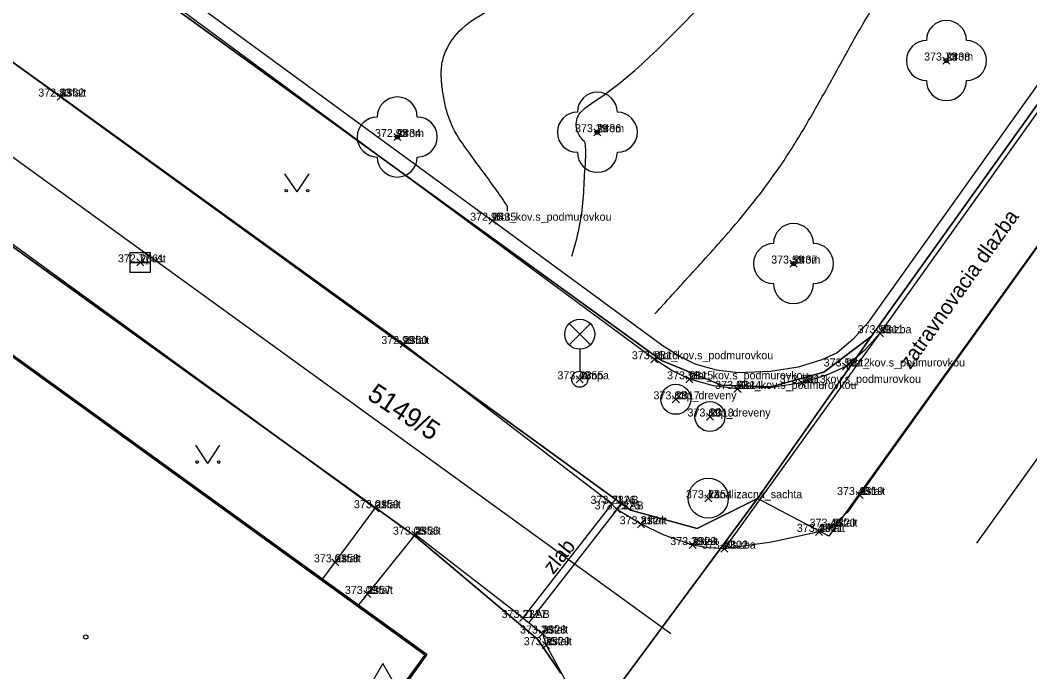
# Model space of a CAD drawing. Extents: x -400488 to -400124, y -1251493 to -1251223.
# Drawn here: x -400314.45 to -400289.23, y -1251399.85 to -1251383.58 of the extents above; entities that cross this region are included whole.
import ezdxf

# ---------------------------------------------------------------- set-up
doc = ezdxf.new("R2010")
doc.units = 0
for name, color, linetype in [('Level 20', 7, 'Continuous'), ('Level 21', 7, 'Continuous'), ('Level 22', 7, 'Continuous'), ('Level 23', 7, 'Continuous'), ('Level 31', 7, 'Continuous'), ('Level 32', 7, 'Continuous'), ('Level 34', 7, 'Continuous'), ('Level 35', 7, 'Continuous'), ('Level 36', 7, 'Continuous'), ('Level 49', 7, 'Continuous'), ('Level 50', 7, 'Continuous'), ('Level 52', 7, 'Continuous'), ('Level 53', 7, 'Continuous'), ('Level 54', 7, 'Continuous'), ('Level 63', 7, 'Continuous')]:
    doc.layers.add(name, color=color, linetype=linetype)

msp = doc.modelspace()

# ---------------------------------------------------------------- linework, layer by layer
at = {"layer": 'Level 20'}
for p, q in [((-400291.398, -1251384.678), (-400291.222, -1251384.502)), ((-400291.222, -1251384.678), (-400291.398, -1251384.502)), ((-400313.528, -1251385.578), (-400313.352, -1251385.402)), ((-400313.352, -1251385.578), (-400313.528, -1251385.402)), ((-400300.118, -1251386.468), (-400299.942, -1251386.292)), ((-400299.942, -1251386.468), (-400300.118, -1251386.292)), ((-400305.118, -1251386.588), (-400304.942, -1251386.412)), ((-400304.942, -1251386.588), (-400305.118, -1251386.412)), ((-400302.738, -1251388.678), (-400302.562, -1251388.502)), ((-400302.562, -1251388.678), (-400302.738, -1251388.502)), ((-400311.538, -1251389.718), (-400311.362, -1251389.542)), ((-400311.362, -1251389.718), (-400311.538, -1251389.542)), ((-400295.218, -1251389.748), (-400295.042, -1251389.572)), ((-400295.042, -1251389.748), (-400295.218, -1251389.572)), ((-400293.058, -1251391.488), (-400292.882, -1251391.312)), ((-400292.882, -1251391.488), (-400293.058, -1251391.312)), ((-400304.958, -1251391.758), (-400304.782, -1251391.582)), ((-400304.782, -1251391.758), (-400304.958, -1251391.582)), ((-400298.698, -1251392.138), (-400298.522, -1251391.962)), ((-400298.522, -1251392.138), (-400298.698, -1251391.962)), ((-400293.908, -1251392.318), (-400293.732, -1251392.142)), ((-400293.732, -1251392.318), (-400293.908, -1251392.142)), ((-400300.558, -1251392.638), (-400300.382, -1251392.462)), ((-400300.382, -1251392.638), (-400300.558, -1251392.462)), ((-400297.818, -1251392.638), (-400297.642, -1251392.462)), ((-400297.642, -1251392.638), (-400297.818, -1251392.462)), ((-400295.008, -1251392.728), (-400294.832, -1251392.552)), ((-400294.832, -1251392.728), (-400295.008, -1251392.552)), ((-400296.618, -1251392.878), (-400296.442, -1251392.702)), ((-400296.442, -1251392.878), (-400296.618, -1251392.702)), ((-400298.158, -1251393.138), (-400297.982, -1251392.962)), ((-400297.982, -1251393.138), (-400298.158, -1251392.962)), ((-400297.308, -1251393.568), (-400297.132, -1251393.392)), ((-400297.132, -1251393.568), (-400297.308, -1251393.392)), ((-400293.568, -1251395.528), (-400293.392, -1251395.352)), ((-400293.392, -1251395.528), (-400293.568, -1251395.352)), ((-400299.758, -1251395.748), (-400299.582, -1251395.572)), ((-400299.582, -1251395.748), (-400299.758, -1251395.572)), ((-400297.348, -1251395.608), (-400297.172, -1251395.432)), ((-400297.172, -1251395.608), (-400297.348, -1251395.432)), ((-400305.668, -1251395.858), (-400305.492, -1251395.682)), ((-400305.492, -1251395.858), (-400305.668, -1251395.682)), ((-400299.628, -1251395.888), (-400299.452, -1251395.712)), ((-400299.452, -1251395.888), (-400299.628, -1251395.712)), ((-400299.028, -1251396.258), (-400298.852, -1251396.082)), ((-400298.852, -1251396.258), (-400299.028, -1251396.082)), ((-400304.668, -1251396.518), (-400304.492, -1251396.342)), ((-400304.492, -1251396.518), (-400304.668, -1251396.342)), ((-400294.578, -1251396.448), (-400294.402, -1251396.272)), ((-400294.402, -1251396.448), (-400294.578, -1251396.272)), ((-400294.258, -1251396.318), (-400294.082, -1251396.142)), ((-400294.082, -1251396.318), (-400294.258, -1251396.142)), ((-400297.738, -1251396.778), (-400297.562, -1251396.602)), ((-400297.562, -1251396.778), (-400297.738, -1251396.602)), ((-400296.948, -1251396.868), (-400296.772, -1251396.692)), ((-400296.772, -1251396.868), (-400296.948, -1251396.692)), ((-400306.668, -1251397.208), (-400306.492, -1251397.032)), ((-400306.492, -1251397.208), (-400306.668, -1251397.032)), ((-400305.868, -1251397.998), (-400305.692, -1251397.822)), ((-400305.692, -1251397.998), (-400305.868, -1251397.822)), ((-400301.978, -1251398.598), (-400301.802, -1251398.422)), ((-400301.802, -1251398.598), (-400301.978, -1251398.422)), ((-400301.488, -1251398.988), (-400301.312, -1251398.812)), ((-400301.312, -1251398.988), (-400301.488, -1251398.812)), ((-400301.398, -1251399.278), (-400301.222, -1251399.102)), ((-400301.222, -1251399.278), (-400301.398, -1251399.102))]:
    msp.add_line(p, q, dxfattribs=at)
at = {"layer": 'Level 31'}
for points in [[(-400292.97, -1251391.4), (-400296.86, -1251396.78)], [(-400299.67, -1251395.66), (-400301.89, -1251398.51)], [(-400299.54, -1251395.8), (-400301.742, -1251398.627)]]:
    msp.add_lwpolyline(points, dxfattribs=at)
at = {"layer": 'Level 32'}
msp.add_line((-400290.55, -1251396.645), (-400264.548, -1251360.319), dxfattribs=at)
for points in [[(-400270.68, -1251354.37), (-400269.393, -1251355.452), (-400268.89, -1251355.918), (-400268.52, -1251356.37), (-400268.265, -1251356.83), (-400268.08, -1251357.34), (-400267.96, -1251358.23), (-400267.913, -1251358.721), (-400267.9, -1251359.2), (-400268.092, -1251359.586), (-400270.52, -1251363.46), (-400278.03, -1251373.86), (-400293.48, -1251395.44), (-400293.769, -1251395.863), (-400294.17, -1251396.23), (-400294.49, -1251396.36), (-400295.676, -1251396.619), (-400296.86, -1251396.78), (-400297.255, -1251396.759), (-400297.65, -1251396.69), (-400298.36, -1251396.445), (-400298.94, -1251396.17), (-400299.54, -1251395.8), (-400299.67, -1251395.66)], [(-400313.44, -1251385.49), (-400321.58, -1251379.65), (-400332, -1251372.55)], [(-400298.195, -1251398.906), (-400330.918, -1251375.214)], [(-400331.04, -1251377.23), (-400305.58, -1251395.77), (-400331.355, -1251377.021), (-400331.659, -1251376.849), (-400331.92, -1251376.772), (-400332.18, -1251376.74), (-400332.684, -1251376.866), (-400333.069, -1251377.004), (-400333.432, -1251377.178), (-400333.85, -1251377.49), (-400335, -1251379.01), (-400336.633, -1251381.335)], [(-400299.67, -1251395.66), (-400304.87, -1251391.67), (-400313.44, -1251385.49)], [(-400306.913, -1251397.57), (-400305.58, -1251395.77)], [(-400301.89, -1251398.51), (-400304.58, -1251396.43), (-400306.025, -1251398.213)], [(-400301.89, -1251398.51), (-400301.4, -1251398.9), (-400301.31, -1251399.19), (-400300.26, -1251401.11), (-400300.19, -1251401.36), (-400300.045, -1251402.48), (-400299.98, -1251403.97), (-400300.164, -1251404.567), (-400300.47, -1251405.17), (-400303.28, -1251409.37)]]:
    msp.add_lwpolyline(points, dxfattribs=at)
at = {"layer": 'Level 34'}
msp.add_lwpolyline([(-400333.76, -1251378.15), (-400304.338, -1251399.434), (-400304.338, -1251399.434), (-400309.014, -1251405.829)], dxfattribs=at)
at = {"layer": 'Level 35'}
for points in [[(-400330.938, -1251368.394), (-400330.78, -1251368.19), (-400329.16, -1251369.12), (-400314.31, -1251380.06), (-400302.65, -1251388.59)], [(-400279.695, -1251372.087), (-400293.283, -1251391.15), (-400293.637, -1251391.547), (-400294.036, -1251391.888), (-400294.424, -1251392.061), (-400295.012, -1251392.25), (-400295.704, -1251392.357), (-400296.513, -1251392.389), (-400297.052, -1251392.322), (-400297.586, -1251392.175), (-400297.973, -1251391.981), (-400298.384, -1251391.72), (-400302.65, -1251388.59)], [(-400279.37, -1251372.32), (-400292.97, -1251391.4), (-400293.356, -1251391.833), (-400293.82, -1251392.23), (-400294.281, -1251392.435), (-400294.92, -1251392.64), (-400295.666, -1251392.756), (-400296.53, -1251392.79), (-400297.13, -1251392.716), (-400297.73, -1251392.55), (-400298.17, -1251392.329), (-400298.61, -1251392.05), (-400311.61, -1251382.45), (-400320.06, -1251376.29)]]:
    msp.add_lwpolyline(points, dxfattribs=at)
at = {"layer": 'Level 36'}
for p, q in [((-400307.534, -1251387.87), (-400307.834, -1251387.42)), ((-400307.534, -1251387.87), (-400307.234, -1251387.42)), ((-400309.758, -1251394.649), (-400310.058, -1251394.199)), ((-400309.758, -1251394.649), (-400309.458, -1251394.199))]:
    msp.add_line(p, q, dxfattribs=at)
for centre, radius in [((-400291.31, -1251384.59), 0.05), ((-400305.03, -1251386.5), 0.05), ((-400300.03, -1251386.38), 0.05), ((-400307.804, -1251387.84), 0.03), ((-400307.264, -1251387.84), 0.03), ((-400295.13, -1251389.66), 0.05), ((-400310.028, -1251394.619), 0.03), ((-400309.488, -1251394.619), 0.03)]:
    msp.add_circle(centre, radius, dxfattribs=at)
for centre, start, end in [((-400291.31, -1251384.09), 0, 180), ((-400291.81, -1251384.59), 90, 270), ((-400290.81, -1251384.59), 270, 90), ((-400291.31, -1251385.09), 180, 0), ((-400305.03, -1251386), 0, 180), ((-400300.03, -1251385.88), 0, 180), ((-400305.53, -1251386.5), 90, 270), ((-400304.53, -1251386.5), 270, 90), ((-400300.53, -1251386.38), 90, 270), ((-400299.53, -1251386.38), 270, 90), ((-400305.03, -1251387), 180, 0), ((-400300.03, -1251386.88), 180, 0), ((-400295.13, -1251389.16), 0, 180), ((-400295.63, -1251389.66), 90, 270), ((-400294.63, -1251389.66), 270, 90), ((-400295.13, -1251390.16), 180, 0)]:
    msp.add_arc(centre, 0.5, start, end, dxfattribs=at)
at = {"layer": 'Level 49'}
for points in [[(-400298.594, -1251390.918), (-400297.579, -1251389.803), (-400296.576, -1251388.675), (-400295.294, -1251386.973), (-400294.717, -1251386.031), (-400294.176, -1251385.068), (-400293.64, -1251384.103), (-400293.079, -1251383.154), (-400292.558, -1251382.354), (-400292.017, -1251381.567), (-400291.474, -1251380.779), (-400290.946, -1251379.978), (-400290.936, -1251379.958), (-400290.353, -1251377.108), (-400290.345, -1251377.073), (-400289.148, -1251371.673), (-400289.131, -1251371.633), (-400288.68, -1251369.757), (-400288.682, -1251369.751), (-400289.179, -1251365.184), (-400289.187, -1251365.045), (-400289.199, -1251364.086), (-400289.178, -1251363.127), (-400289.151, -1251362.167), (-400289.146, -1251361.208), (-400289.326, -1251359.947), (-400289.998, -1251358.61), (-400290.194, -1251358.383), (-400290.2, -1251358.378), (-400291.608, -1251356.855), (-400292.307, -1251356.088), (-400293.021, -1251355.336), (-400293.116, -1251355.24), (-400296.365, -1251351.788), (-400297.616, -1251350.178), (-400299.549, -1251347.891), (-400299.559, -1251347.877), (-400299.595, -1251347.847), (-400301.142, -1251346.859), (-400302.556, -1251345.879), (-400307.962, -1251342.189), (-400307.971, -1251342.179), (-400307.982, -1251342.152), (-400308.883, -1251340.471), (-400309.528, -1251339.56), (-400310.26, -1251338.706), (-400310.968, -1251337.837), (-400311.406, -1251337.164)], [(-400300.667, -1251389.478), (-400300.483, -1251388.773), (-400300.384, -1251388.062), (-400300.344, -1251387.35), (-400300.339, -1251386.641), (-400300.34, -1251386.636), (-400300.362, -1251386.605), (-400300.534, -1251386.354), (-400300.515, -1251385.99), (-400300.109, -1251385.615), (-400297.14, -1251382.932), (-400297.057, -1251382.855), (-400295.589, -1251381.52), (-400295.422, -1251381.289), (-400295.284, -1251381.059), (-400295.265, -1251381.015), (-400294.968, -1251379.948), (-400294.642, -1251379.013), (-400294.274, -1251378.09), (-400293.924, -1251377.161), (-400293.647, -1251376.207), (-400293.646, -1251376.19), (-400293.641, -1251376.158), (-400292.799, -1251374.602), (-400292.78, -1251374.568), (-400292.201, -1251371.517), (-400292.573, -1251371.086), (-400292.863, -1251370.616), (-400292.873, -1251370.59), (-400293.119, -1251369.55), (-400293.291, -1251368.49), (-400293.49, -1251367.439), (-400293.821, -1251366.425), (-400295.335, -1251363.46), (-400297.084, -1251360.63), (-400298.379, -1251358.699), (-400299.238, -1251357.272), (-400300.054, -1251355.818), (-400300.862, -1251354.357), (-400301.693, -1251352.905), (-400302.556, -1251351.775), (-400302.586, -1251351.768), (-400302.595, -1251351.766), (-400303.457, -1251351.41), (-400304.217, -1251350.882), (-400305.536, -1251349.48), (-400306.763, -1251347.91), (-400307.407, -1251347.171), (-400308.106, -1251346.519), (-400308.834, -1251345.958), (-400309.579, -1251345.414), (-400310.323, -1251344.863), (-400311.049, -1251344.285), (-400311.07, -1251344.262), (-400311.075, -1251344.251), (-400312.804, -1251340.258), (-400313.009, -1251339.843), (-400313.235, -1251339.439), (-400313.463, -1251339.034), (-400313.486, -1251338.992)], [(-400302.274, -1251388.348), (-400302.272, -1251388.271), (-400302.278, -1251388.233), (-400302.281, -1251388.228), (-400302.591, -1251387.772), (-400302.918, -1251387.325), (-400303.243, -1251386.879), (-400303.551, -1251386.426), (-400303.823, -1251385.744), (-400303.889, -1251385.388), (-400303.927, -1251385.033), (-400303.913, -1251384.678), (-400303.803, -1251384.323), (-400303.411, -1251383.791), (-400302.671, -1251383.29), (-400301.914, -1251382.832), (-400301.154, -1251382.385), (-400300.407, -1251381.918), (-400299.486, -1251381.332), (-400299.035, -1251381.021), (-400298.814, -1251380.857), (-400298.596, -1251380.685), (-400297.82, -1251379.213), (-400297.067, -1251376.761)]]:
    msp.add_spline(points, degree=3, dxfattribs=at)
at = {"layer": 'Level 50'}
msp.add_lwpolyline([(-400305.39, -1251399.646), (-400306.39, -1251401.377), (-400304.39, -1251401.377)], close=True, dxfattribs=at)
at = {"layer": 'Level 52'}
msp.add_lwpolyline([(-400311.7, -1251389.63), (-400311.7, -1251389.38), (-400311.2, -1251389.38), (-400311.2, -1251389.63)], dxfattribs=at)
msp.add_lwpolyline([(-400311.7, -1251389.63), (-400311.2, -1251389.63), (-400311.2, -1251389.88), (-400311.7, -1251389.88)], close=True, dxfattribs=at)
msp.add_circle((-400297.26, -1251395.52), 0.5, dxfattribs=at)
at = {"layer": 'Level 53'}
for p, q in [((-400300.735, -1251391.69), (-400300.205, -1251391.16)), ((-400300.205, -1251391.16), (-400300.735, -1251391.69)), ((-400300.205, -1251391.69), (-400300.735, -1251391.16)), ((-400300.47, -1251391.8), (-400300.47, -1251392.35))]:
    msp.add_line(p, q, dxfattribs=at)
for centre, radius in [((-400300.47, -1251391.425), 0.375), ((-400300.47, -1251392.55), 0.2)]:
    msp.add_circle(centre, radius, dxfattribs=at)
at = {"layer": 'Level 54'}
for centre in [(-400298.07, -1251393.05), (-400297.22, -1251393.48)]:
    msp.add_circle(centre, 0.375, dxfattribs=at)
at = {"layer": 'Level 63'}
for p, q in [((-400293.18, -1251391.47), (-400270.09, -1251359.2)), ((-400270.09, -1251359.2), (-400293.18, -1251391.47)), ((-400267.74, -1251359.55), (-400294.25, -1251396.47)), ((-400298.43, -1251392.08), (-400336.35, -1251364.63)), ((-400336.35, -1251364.63), (-400298.43, -1251392.08)), ((-400315.82, -1251383.78), (-400299.2, -1251395.82)), ((-400299.2, -1251395.82), (-400315.82, -1251383.78)), ((-400304.57, -1251396.48), (-400318.01, -1251386.82)), ((-400318.01, -1251386.82), (-400304.57, -1251396.48)), ((-400319.29, -1251388.59), (-400304.29, -1251399.42)), ((-400304.29, -1251399.42), (-400319.29, -1251388.59)), ((-400296.03, -1251395.53), (-400293.18, -1251391.47)), ((-400293.18, -1251391.47), (-400296.03, -1251395.53)), ((-400293.18, -1251391.47), (-400294.37, -1251392.37)), ((-400294.37, -1251392.37), (-400293.18, -1251391.47)), ((-400296.93, -1251392.7), (-400298.43, -1251392.08)), ((-400298.43, -1251392.08), (-400296.93, -1251392.7)), ((-400294.37, -1251392.37), (-400295.7, -1251392.74)), ((-400295.7, -1251392.74), (-400294.37, -1251392.37)), ((-400295.7, -1251392.74), (-400296.93, -1251392.7)), ((-400296.93, -1251392.7), (-400295.7, -1251392.74)), ((-400300.33, -1251401.33), (-400296.03, -1251395.53)), ((-400296.03, -1251395.53), (-400300.33, -1251401.33)), ((-400297.54, -1251396.28), (-400296.03, -1251395.53)), ((-400296.03, -1251395.53), (-400297.54, -1251396.28)), ((-400294.25, -1251396.47), (-400296.03, -1251395.53)), ((-400299.2, -1251395.82), (-400297.54, -1251396.28)), ((-400297.54, -1251396.28), (-400299.2, -1251395.82)), ((-400301.53, -1251399.04), (-400304.57, -1251396.48)), ((-400304.57, -1251396.48), (-400301.53, -1251399.04)), ((-400300.94, -1251399.89), (-400301.53, -1251399.04)), ((-400301.53, -1251399.04), (-400300.94, -1251399.89)), ((-400304.29, -1251399.42), (-400311.14, -1251408.98)), ((-400311.14, -1251408.98), (-400304.29, -1251399.42))]:
    msp.add_line(p, q, dxfattribs=at)
msp.add_circle((-400312.81, -1251398.986), 0.054, dxfattribs=at)

# ---------------------------------------------------------------- texts
at = {"layer": 'Level 21'}
for s, p in [('2438', (-400291.31, -1251384.59)), ('2362', (-400313.44, -1251385.49)), ('2434', (-400305.03, -1251386.5)), ('2436', (-400300.03, -1251386.38)), ('2435', (-400302.65, -1251388.59)), ('2361', (-400311.45, -1251389.63)), ('2437', (-400295.13, -1251389.66)), ('2311', (-400292.97, -1251391.4)), ('2360', (-400304.87, -1251391.67)), ('2316', (-400298.61, -1251392.05)), ('2312', (-400293.82, -1251392.23)), ('2355', (-400300.47, -1251392.55)), ('2315', (-400297.73, -1251392.55)), ('2314', (-400296.53, -1251392.79)), ('2313', (-400294.92, -1251392.64)), ('2317', (-400298.07, -1251393.05)), ('2318', (-400297.22, -1251393.48)), ('2354', (-400297.26, -1251395.52)), ('2319', (-400293.48, -1251395.44)), ('2359', (-400305.58, -1251395.77)), ('2326', (-400299.67, -1251395.66)), ('2325', (-400299.54, -1251395.8)), ('2324', (-400298.94, -1251396.17)), ('2320', (-400294.17, -1251396.23)), ('2356', (-400304.58, -1251396.43)), ('2321', (-400294.49, -1251396.36)), ('2323', (-400297.65, -1251396.69)), ('2322', (-400296.86, -1251396.78)), ('2358', (-400306.58, -1251397.12)), ('2357', (-400305.78, -1251397.91)), ('2327', (-400301.89, -1251398.51)), ('2328', (-400301.4, -1251398.9)), ('2329', (-400301.31, -1251399.19))]:
    msp.add_text(s, height=0.2, dxfattribs=at).set_placement(p)
at = {"layer": 'Level 22'}
for s, p in [('strom', (-400291.31, -1251384.59)), ('asfalt', (-400313.44, -1251385.49)), ('strom', (-400300.03, -1251386.38)), ('strom', (-400305.03, -1251386.5)), ('plot_kov.s_podmurovkou', (-400302.65, -1251388.59)), ('vpust', (-400311.45, -1251389.63)), ('strom', (-400295.13, -1251389.66)), ('dlazba', (-400292.97, -1251391.4)), ('asfalt', (-400304.87, -1251391.67)), ('plot_kov.s_podmurovkou', (-400298.61, -1251392.05)), ('plot_kov.s_podmurovkou', (-400293.82, -1251392.23)), ('lampa', (-400300.47, -1251392.55)), ('plot_kov.s_podmurovkou', (-400297.73, -1251392.55)), ('plot_kov.s_podmurovkou', (-400296.53, -1251392.79)), ('plot_kov.s_podmurovkou', (-400294.92, -1251392.64)), ('stlp_dreveny', (-400298.07, -1251393.05)), ('stlp_dreveny', (-400297.22, -1251393.48)), ('kanalizacna_sachta', (-400297.26, -1251395.52)), ('asfalt', (-400293.48, -1251395.44)), ('asfalt', (-400305.58, -1251395.77)), ('ZLAB', (-400299.67, -1251395.66)), ('ZLAB', (-400299.54, -1251395.8)), ('asfalt', (-400298.94, -1251396.17)), ('asfalt', (-400294.17, -1251396.23)), ('asfalt', (-400304.58, -1251396.43)), ('asfalt', (-400294.49, -1251396.36)), ('asfalt', (-400297.65, -1251396.69)), ('dlazba', (-400296.86, -1251396.78)), ('asfalt', (-400306.58, -1251397.12)), ('asfalt', (-400305.78, -1251397.91)), ('ZLAB', (-400301.89, -1251398.51)), ('asfalt', (-400301.4, -1251398.9)), ('asfalt', (-400301.31, -1251399.19))]:
    msp.add_text(s, height=0.2, dxfattribs=at).set_placement(p)
at = {"layer": 'Level 23'}
for s, p in [('373.73', (-400291.868, -1251384.59)), ('372.83', (-400313.998, -1251385.49)), ('372.93', (-400305.588, -1251386.5)), ('373.29', (-400300.588, -1251386.38)), ('372.95', (-400303.209, -1251388.59)), ('372.77', (-400312.008, -1251389.63)), ('373.59', (-400295.688, -1251389.66)), ('373.59', (-400293.528, -1251391.4)), ('372.99', (-400305.428, -1251391.67)), ('373.55', (-400299.169, -1251392.05)), ('373.59', (-400294.378, -1251392.23)), ('373.48', (-400301.028, -1251392.55)), ('373.59', (-400298.288, -1251392.55)), ('373.63', (-400297.088, -1251392.79)), ('373.58', (-400295.478, -1251392.64)), ('373.63', (-400298.628, -1251393.05)), ('373.69', (-400297.778, -1251393.48)), ('373.47', (-400297.818, -1251395.52)), ('373.46', (-400294.043, -1251395.44)), ('373.01', (-400306.113, -1251395.77)), ('373.21', (-400300.203, -1251395.66)), ('373.25', (-400300.099, -1251395.8)), ('373.31', (-400299.473, -1251396.17)), ('373.45', (-400294.729, -1251396.23)), ('373.05', (-400305.139, -1251396.43)), ('373.47', (-400295.048, -1251396.36)), ('373.39', (-400298.208, -1251396.69)), ('373.42', (-400297.418, -1251396.78)), ('373.01', (-400307.113, -1251397.12)), ('373.09', (-400306.338, -1251397.91)), ('373.21', (-400302.423, -1251398.51)), ('373.26', (-400301.963, -1251398.9)), ('373.35', (-400301.869, -1251399.19))]:
    msp.add_text(s, height=0.2, dxfattribs=at).set_placement(p)
at = {"layer": 'Level 31'}
for s, rotation, p in [('zatravnovacia dlazba', 54.566, (-400292.214, -1251392.322)), ('zlab', 51.2492, (-400301.133, -1251397.443))]:
    msp.add_text(s, height=0.375, rotation=rotation, dxfattribs=at).set_placement(p)
at = {"layer": 'Level 63'}
msp.add_text('5149/5', height=0.48, rotation=326.7677, dxfattribs=at).set_placement((-400305.809, -1251393.023))

doc.saveas('drawing.dxf')
